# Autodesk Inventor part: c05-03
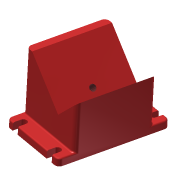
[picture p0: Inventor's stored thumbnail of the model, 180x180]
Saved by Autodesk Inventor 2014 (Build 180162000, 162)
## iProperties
Created: 2010-11
Part Number: c05-03
Material: Generic
Document SubType Name: Modeling
Designer: Thom Tremblay
Density: 1 g/cm^3
Appearance: Satin -Light Red
Author: Thom Tremblay
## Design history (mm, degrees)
sketch "Sketch1"
  geometry: L1 (-45, 0)-(45, 0); L2 (45, 0)-(45, 10); L3 (45, 10)-(-45, 10); L4 (-45, 10)-(-45, 0); L5 (-45, 10)-(-45, 90); L6 (-45, 90)-(-35, 90); L7 (-35, 90)-(14.497, 40.503); L8 (14.497, 40.503)-(45, 71.005); L9 (45, 71.005)-(45, 10); 2 further points
  constraints: 18 end point, 4 perpendicular, 3 collinear, 2 parallel, 2 point on line, 1 coincident, 1 horizontal, 1 midpoint
  dimensions: "d0" = 90 distance of L3.end L2.end; "d1" = 10 distance of L2.end L1.end; "d2" = 80 distance of L5.start L5.end; "d3" = 10 distance of L5.end L6.end; "d4" = 70 distance of L6.end L7.end; "d5" = 135 deg angle of L6 L7
extrude "Extrusion1" new body sketch "Sketch1" stored distance "d8" = 100; taper "d9" = 0 deg
extrude "Extrusion2" join sketch "Sketch1" stored distance "d10" = 140; taper "d11" = 0 deg
fillet "Fillet1" dims "d12" = 6
fillet "Fillet2" dims "d13" = 2
sketch "Sketch2"
  geometry: L1 (78, -2)-(0, -2) reference; L2 (-6, 4)-(-6, 132) reference; L3 (4.5, -2)-(13.5, -2); L4 (13.5, -2)-(13.5, 8); L5 (13.5, 8)-(4.5, 8); L6 (4.5, 8)-(4.5, -2); 2 further points
  constraints: 8 end point, 2 parallel, 1 horizontal, 1 horizontal alignment, 1 midpoint, 1 perpendicular, 1 point on line, 2 other
  dimensions: "d14" = 9 distance of L5.end L4.end; "d15" = 10 distance of L4.end L3.end; "d16" = 15 distance from line of point (9, 8) L2
extrude "Extrusion3" cut sketch "Sketch2" stored distance "d17" = 140; taper "d18" = 0 deg
mirror "Mirror1"
mirror "Mirror2"
hole "Hole1" diameter "d21" = 8.376; stored, may be unused: countersink angle "d25" = 90 deg, drill point angle "d27" = 118 deg; dims "d19" = 50, "d20" = 14, "d22" = 30, "d23" = 4, "d24" = 2, "d26" = 33
body "Solid1"
